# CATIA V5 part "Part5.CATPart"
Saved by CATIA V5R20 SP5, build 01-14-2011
Part number: 螺母
Bounding box of the stored display mesh (mm): x -57.598 to 57.598, y -49.993 to 49.993, z -15 to 15
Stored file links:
  E:\scc\Part5.CATPart
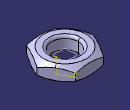
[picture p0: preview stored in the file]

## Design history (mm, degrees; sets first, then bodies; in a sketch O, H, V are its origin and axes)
Body1 (main body)
  Sketch1 on xy-plane, origin (0, 0, 0), H (1, 0, 0), V (0, 1, 0)
    point P1 (28.9918, -49.7706)
    point P2 (57.5985, 0.2224)
    point P3 (28.6066, 49.9929)
    point P4 (-28.9918, 49.7706)
    point P5 (-57.5985, -0.2224)
    point P6 (-28.6066, -49.9929)
    point P7 (43.2952, -24.7741)
    line L1 (28.9918, -49.7706) -> (57.5985, 0.2224)
    line L2 (57.5985, 0.2224) -> (28.6066, 49.9929)
    line L3 (28.6066, 49.9929) -> (-28.9918, 49.7706)
    line L4 (-28.9918, 49.7706) -> (-57.5985, -0.2224)
    line L5 (-57.5985, -0.2224) -> (-28.6066, -49.9929)
    line L6 (-28.6066, -49.9929) -> (28.9918, -49.7706)
    construction line L7 (0, 0) -> (43.2952, -24.7741)
    construction circle A1 centre (0, 0) radius 57.5989
    construction arc A2 centre (-57.5985, -0.2224) radius 57.5989 from (-28.9918, 49.7706) to (-28.6066, -49.9929) cw
    construction arc A3 centre (57.5985, 0.2224) radius 57.5989 from (28.6066, 49.9929) to (28.9918, -49.7706) ccw
    circle A4 centre (0, 0) radius 27.1467
    coincidence: A1 P1, A1 P2, A1 P3, A1 P4, A1 P5, A1 P6, A2 O, A3 O
    midpoint: P7 L1
    parallelism: L1 L4
  Pad1: profile Sketch1, direction (0, 0, 1), length 15, mirrored extent
  Sketch2 on face of Pad1 from Sketch1.L2, origin (43.1026, 25.1077, 0), H (-0.5033, 0.8641, 0), V (0, 0, 1)
    point P1 (25, 15)
  Sketch3 on face of Pad1 from Sketch1.L2, origin (43.1026, 25.1077, 0), H (-0.5033, 0.8641, 0), V (0, 0, 1)
  Sketch4 on face of Pad1 from Sketch1.L2, origin (43.1026, 25.1077, 0), H (-0.5033, 0.8641, 0), V (0, 0, 1)
  Sketch5 on zx-plane, origin (0, 0, 0), H (-1, 0, 0), V (0, 0, 1)
    line L1 (43.3807, 15) -> (75.2412, 15)
    line L2 (75.2412, 15) -> (75.2412, -3.3947)
    line L3 (75.2412, -3.3947) -> (43.3807, 15)
    reference projected line E1 (-28.6066, 15) -> (28.9918, 15) from edge [face of Pad1 from Sketch1.L3 | end face of Pad1]
    angle L1 L3 = 30
    horizontal: L1 H
    vertical: L2 V
    coincidence: L1 E1
  Groove1: profile Sketch5, axis Sketch5.V, angle 360
  Mirror1: of Groove1, about xy-plane
  Thread1: diameter 59.7227, depth 10, pitch 1, on face of Pad1 from Sketch1.A4, from end face of Pad1
  Fillet1: radius 5, on edge [end face of Pad1 | face of Pad1 from Sketch1.A4]
  Fillet2: radius 5, on edge [face of Pad1 from Sketch1.A4 | start face of Pad1]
